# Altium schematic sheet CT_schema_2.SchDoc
size 379 x 228 mm
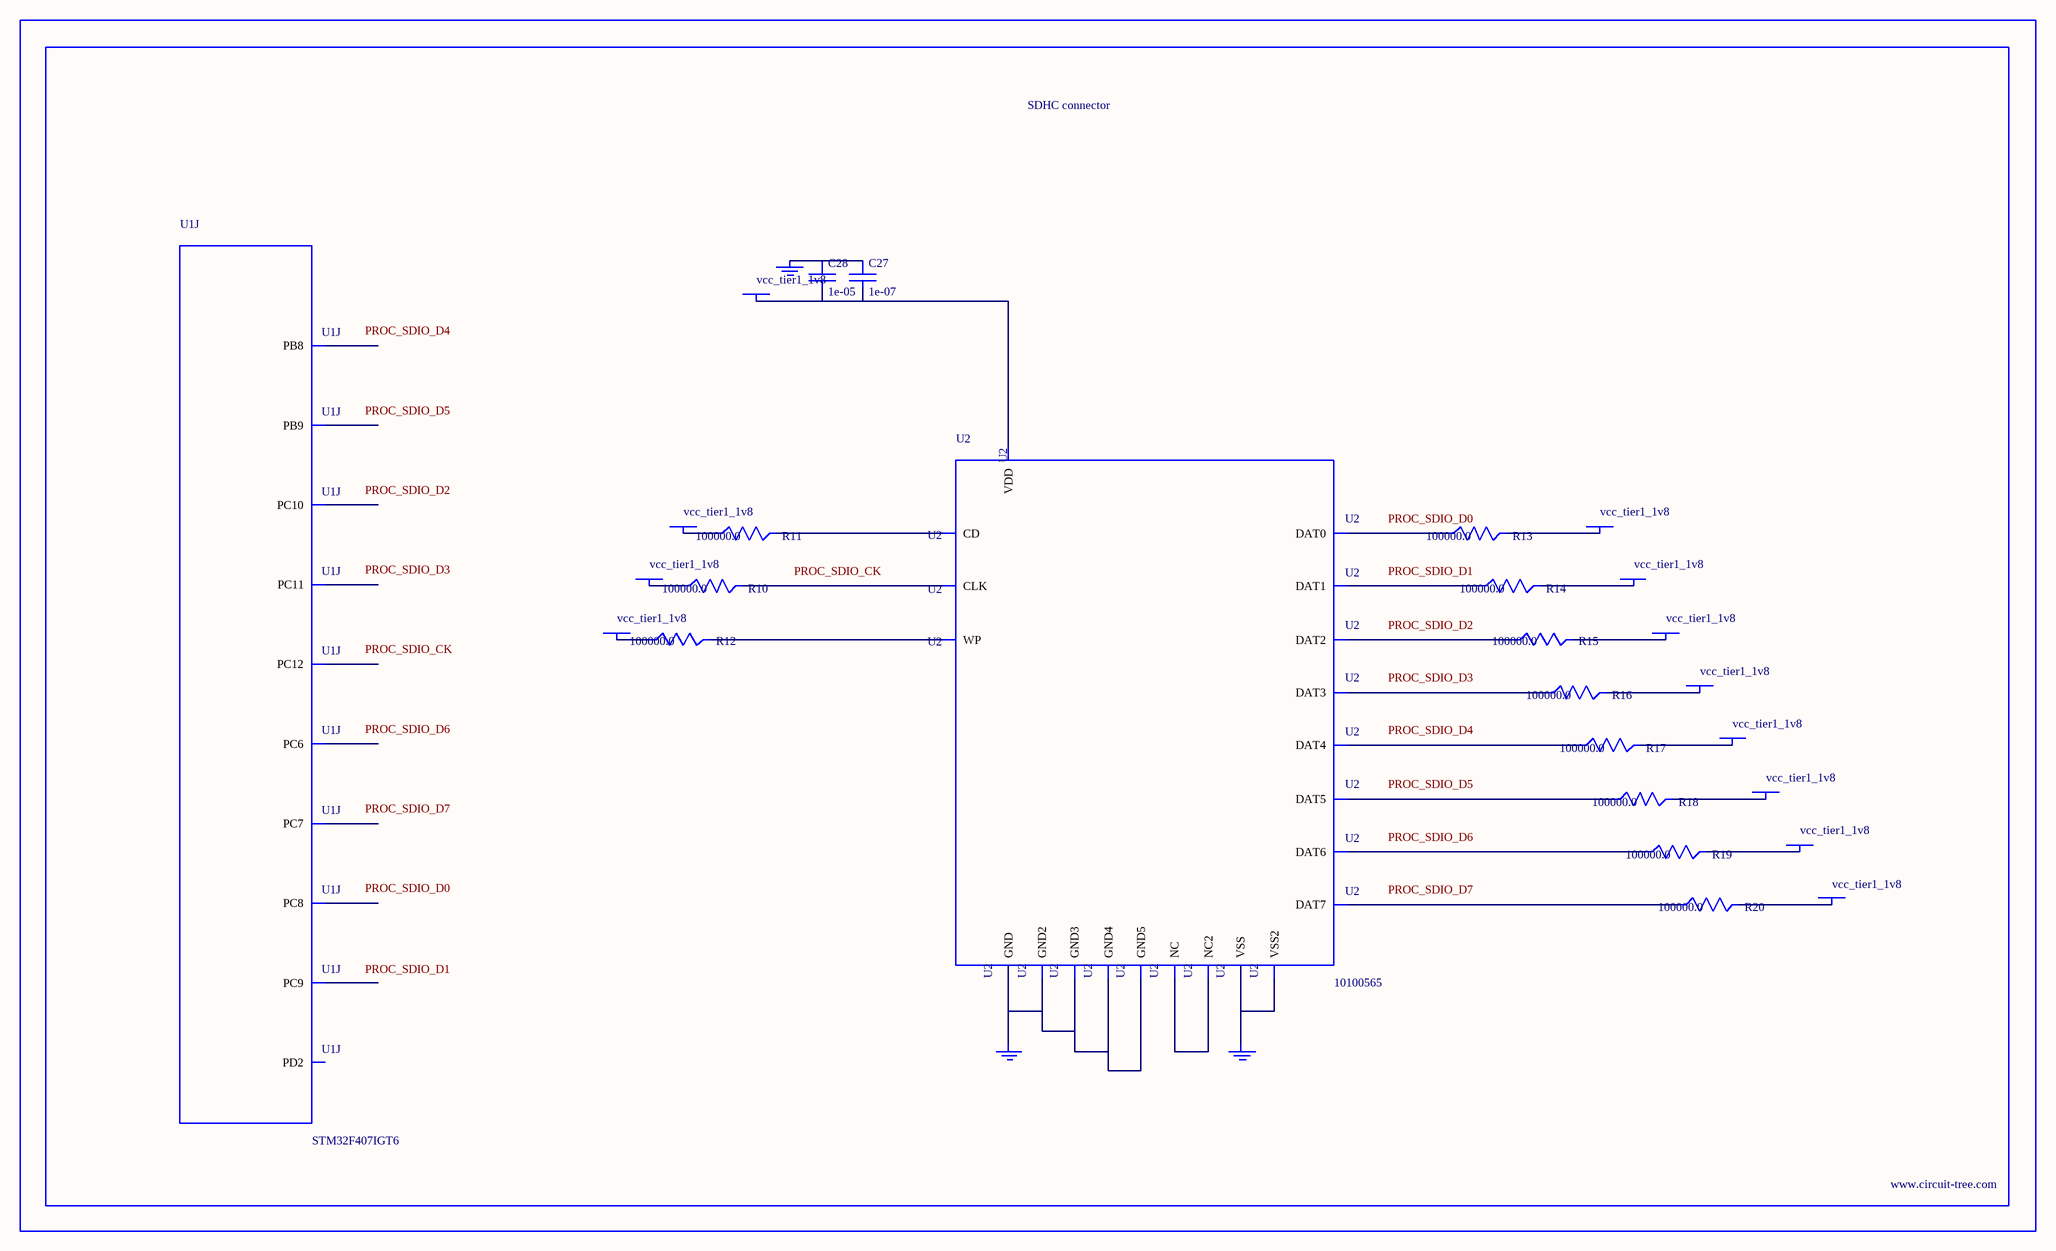
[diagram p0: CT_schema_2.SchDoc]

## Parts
BORDER1  (no value)
C27  1e-07  [C0402]
C28  1e-05  [C0805]
GND_INSTANCE_1_0  (no value)
GND_INSTANCE_1_1  (no value)
GND_INSTANCE_1_2  (no value)
POWER_INSTANCE_1_0  vcc_tier1_1v8
POWER_INSTANCE_1_1  vcc_tier1_1v8
POWER_INSTANCE_1_2  vcc_tier1_1v8
POWER_INSTANCE_1_3  vcc_tier1_1v8
POWER_INSTANCE_1_4  vcc_tier1_1v8
POWER_INSTANCE_1_5  vcc_tier1_1v8
POWER_INSTANCE_1_6  vcc_tier1_1v8
POWER_INSTANCE_1_7  vcc_tier1_1v8
POWER_INSTANCE_1_8  vcc_tier1_1v8
POWER_INSTANCE_1_9  vcc_tier1_1v8
POWER_INSTANCE_1_10  vcc_tier1_1v8
POWER_INSTANCE_1_11  vcc_tier1_1v8
R10  100000.0  [R0603]
R11  100000.0  [R0603]
R12  100000.0  [R0603]
R13  100000.0  [R0603]
R14  100000.0  [R0603]
R15  100000.0  [R0603]
R16  100000.0  [R0603]
R17  100000.0  [R0603]
R18  100000.0  [R0603]
R19  100000.0  [R0603]
R20  100000.0  [R0603]
U1  STM32F407IGT6  [LQFP176]  (part J of 14)
U2  10100565  [10100565]

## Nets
NetC27_1: C27.1 C28.1 GND_INSTANCE_1_0.0(GND)
NetC27_2: C27.2 C28.2 POWER_INSTANCE_1_7.0(PWR) U2.9(VDD)
NetGND_INSTANCE_1_1_0: GND_INSTANCE_1_1.0(GND) U2.6(VSS) U2.10(VSS2)
NetGND_INSTANCE_1_2_0: GND_INSTANCE_1_2.0(GND) U2.12(GND) U2.16(GND2) U2.17(GND3) U2.20(GND4) U2.21(GND5)
NetPOWER_INSTANCE_1_0_0: POWER_INSTANCE_1_0.0(PWR) R12.1
NetPOWER_INSTANCE_1_1_0: POWER_INSTANCE_1_1.0(PWR) R11.1
NetPOWER_INSTANCE_1_2_0: POWER_INSTANCE_1_2.0(PWR) R14.2
NetPOWER_INSTANCE_1_3_0: POWER_INSTANCE_1_3.0(PWR) R13.2
NetPOWER_INSTANCE_1_4_0: POWER_INSTANCE_1_4.0(PWR) R20.2
NetPOWER_INSTANCE_1_5_0: POWER_INSTANCE_1_5.0(PWR) R19.2
NetPOWER_INSTANCE_1_6_0: POWER_INSTANCE_1_6.0(PWR) R10.1
NetPOWER_INSTANCE_1_8_0: POWER_INSTANCE_1_8.0(PWR) R18.2
NetPOWER_INSTANCE_1_9_0: POWER_INSTANCE_1_9.0(PWR) R17.2
NetPOWER_INSTANCE_1_10_0: POWER_INSTANCE_1_10.0(PWR) R16.2
NetPOWER_INSTANCE_1_11_0: POWER_INSTANCE_1_11.0(PWR) R15.2
NetR10_2: R10.2 U2.8(CLK)
NetR11_2: R11.2 U2.2(CD)
NetR12_2: R12.2 U2.1(WP)
NetR13_1: R13.1 U2.4(DAT0)
NetR14_1: R14.1 U2.3(DAT1)
NetR15_1: R15.1 U2.15(DAT2)
NetR16_1: R16.1 U2.14(DAT3)
NetR17_1: R17.1 U2.13(DAT4)
NetR18_1: R18.1 U2.11(DAT5)
NetR19_1: R19.1 U2.7(DAT6)
NetR20_1: R20.1 U2.5(DAT7)
NetU2_18: U2.18(NC) U2.19(NC2)

Not connected (* = marked no-connect by the designer): U1 115(PC6) 116(PC7) 117(PC8) 118(PC9) 139(PC10) 140(PC11) 141(PC12) 144(PD2) 167(PB8) 168(PB9)

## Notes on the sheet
- Labels drawn without touching a wire or pin: PROC_SDIO_CK, PROC_SDIO_D0, PROC_SDIO_D1, PROC_SDIO_D2, PROC_SDIO_D3, PROC_SDIO_D4, PROC_SDIO_D5, PROC_SDIO_D6, PROC_SDIO_D7

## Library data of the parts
BORDER1 = BORDER_PAGE1
C27 = C0402C104K3RACTU
C28 = C0805C106K8RACTU
GND_INSTANCE_1_0-GND_INSTANCE_1_2 = GND
POWER_INSTANCE_1_0-POWER_INSTANCE_1_11 = PWR
R10-R20 = RC0603JR-07100KL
